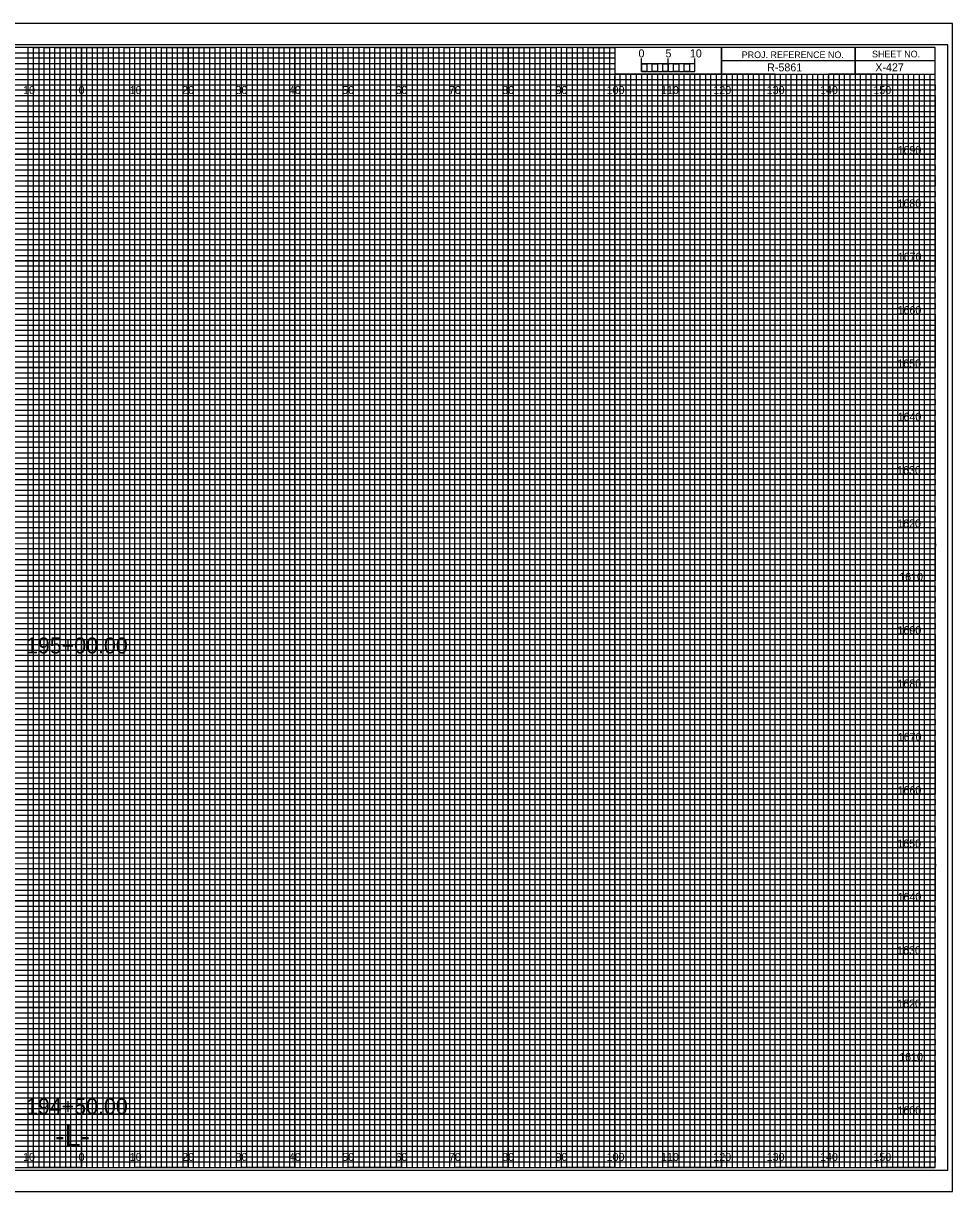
# Model space of a CAD drawing. Extents: x -13 to 323, y -5 to 6154.
# Drawn here: x 149.1 to 323.3, y 5055.5 to 5274.5 of the extents above; entities that cross this region are included whole.
import ezdxf

# ---------------------------------------------------------------- set-up
doc = ezdxf.new("R2010")
doc.units = 0
for name, color, linetype in [('Exist CMT Ground Line', 7, 'Continuous'), ('Prop Horizontal Alignment', 7, 'Continuous'), ('Prop Retaining Wall', 7, 'Continuous'), ('Prop XS Alignment Label', 7, 'Continuous'), ('Prop XS Bar Scale Labels', 7, 'Continuous'), ('Prop XS DDE', 7, 'Continuous'), ('Prop XS DDE Elevations', 7, 'Continuous'), ('Prop XS DDE Slope Text', 7, 'Continuous'), ('Prop XS Earthwork Shape', 7, 'Continuous'), ('Prop XS Elevation Labels', 7, 'Continuous'), ('Prop XS Project Number', 7, 'Continuous'), ('Prop XS Sheet Number', 7, 'Continuous'), ('Prop XS Station Labels', 7, 'Continuous'), ('Raster_Level_0', 7, 'Continuous'), ('Scratch_Level_3', 7, 'Continuous'), ('Sheet Cutting Line CELL', 7, 'Continuous')]:
    doc.layers.add(name, color=color, linetype=linetype)

msp = doc.modelspace()

# ---------------------------------------------------------------- linework, layer by layer
at = {"layer": 'Exist CMT Ground Line'}
for p, q in [((265, 5265.49), (265, 5267.9)), ((265, 5266.9), (265, 5267.9)), ((270, 5265.49), (270, 5267.9)), ((275, 5265.49), (275, 5267.9)), ((275, 5266.9), (275, 5267.9))]:
    msp.add_line(p, q, dxfattribs=at)
for points in [[(275, 5266.9), (265, 5266.9), (265, 5265.49), (275, 5265.49)], [(265, 5266.9), (266, 5266.9), (266, 5265.49), (265, 5265.49)], [(267, 5266.9), (268, 5266.9), (268, 5265.49), (267, 5265.49)], [(269, 5266.9), (270, 5266.9), (270, 5265.49), (269, 5265.49)], [(271, 5266.9), (272, 5266.9), (272, 5265.49), (271, 5265.49)], [(273, 5266.9), (274, 5266.9), (274, 5265.49), (273, 5265.49)]]:
    msp.add_lwpolyline(points, close=True, dxfattribs=at)
at = {"layer": 'Prop Retaining Wall'}
for p, q in [((0, 5269), (260, 5269)), ((260, 5267.98), (0, 5267.98)), ((0, 5267), (260, 5267)), ((260, 5269), (260, 5267.98)), ((260, 5267), (260, 5265.89)), ((260, 5265.89), (0, 5265.89)), ((0, 5264), (320, 5264))]:
    msp.add_line(p, q, dxfattribs=at)
for points in [[(0, 5263), (270, 5263), (320, 5263), (320, 5262), (0, 5262)], [(0, 5261), (320, 5261), (320, 5259), (0, 5259)], [(0, 5258), (320, 5258), (320, 5257), (0, 5256.98)], [(0, 5256), (320, 5256), (320, 5254), (0, 5254)], [(0, 5253), (320, 5253), (320, 5252), (0, 5252)], [(0, 5251), (320, 5251), (320, 5249), (0, 5249)], [(0, 5248), (320, 5248), (320, 5247), (0, 5247)], [(0, 5246), (320, 5246), (320, 5244), (0, 5244)], [(0, 5243), (320, 5243), (320, 5242), (0, 5242)], [(0, 5241), (320, 5241), (320, 5239), (0, 5239)], [(0, 5238), (320, 5238), (320, 5237), (0, 5237)], [(0, 5236), (320, 5236), (320, 5233.95), (320, 5233), (320, 5232), (0, 5232)], [(0, 5234), (320, 5234), (320, 5233), (0, 5233)], [(0, 5231), (320, 5231), (320, 5229), (0, 5229.03)], [(0, 5229.03), (320, 5229), (320, 5228), (0, 5228)], [(0, 5227), (320, 5227), (320, 5226), (0, 5226)], [(0, 5224), (320, 5224), (320, 5223), (0, 5223)], [(0, 5222), (320, 5222), (320, 5221), (0, 5221)], [(-0.07, 5218.89), (320, 5218.89), (320, 5217.88), (-0.07, 5217.88)], [(0, 5217), (320, 5217), (320, 5216), (0, 5216)], [(0, 5214), (320, 5214), (320, 5213), (0, 5213)], [(0, 5212), (320, 5212), (320, 5211), (0, 5211)], [(0, 5209), (320, 5209), (320, 5208), (0, 5208)], [(0, 5207), (320, 5207), (320, 5206), (0, 5206)], [(0, 5204), (320, 5204), (320, 5203), (0, 5203)], [(0, 5202), (320, 5202), (320, 5201), (0, 5201)], [(0, 5199), (320, 5199), (319.99, 5197.98), (0, 5198)], [(0, 5197), (320, 5197), (320, 5196), (0, 5196)], [(0, 5194), (320, 5194), (320, 5193), (0, 5193)], [(0, 5192), (320, 5192), (320, 5191), (0, 5191)], [(0, 5189), (320, 5189), (320, 5188), (0, 5188)], [(0, 5187), (320, 5187), (320, 5186), (0, 5186)], [(0, 5184), (320, 5184), (320, 5183), (0, 5183)], [(0, 5182), (320, 5182), (320, 5181), (0, 5181)], [(0, 5179), (320, 5179), (320, 5178), (0, 5178)], [(0, 5176.99), (320.07, 5176.91), (320, 5176), (0, 5176)], [(0, 5174), (320, 5174), (320, 5173), (0, 5173)], [(0, 5172), (320, 5172), (320, 5171), (0, 5171)], [(0, 5169), (320, 5169), (320, 5168), (0, 5168)], [(0, 5167), (320, 5167), (320, 5166), (0, 5166)], [(0, 5164), (320, 5164), (320, 5163), (0, 5163)], [(0, 5162), (320, 5162), (320, 5161), (0, 5161)], [(0, 5159), (320, 5159), (320, 5158), (0, 5158)], [(0, 5157), (320, 5157), (320, 5156), (0, 5156)], [(0, 5154), (320, 5154), (320, 5153), (0, 5153)], [(0, 5152), (320, 5152), (320, 5151), (0, 5151)], [(0, 5149), (320, 5149), (320, 5148), (0, 5148)], [(0, 5147), (320, 5147), (320, 5146), (0, 5146)], [(0, 5144), (320, 5144), (320, 5143), (0, 5143)], [(0, 5142), (320, 5142), (320, 5141), (0, 5141)], [(0, 5139), (320, 5139), (319.99, 5137.98), (0, 5138)], [(0, 5137), (320, 5137), (320, 5136), (0, 5136)], [(0, 5134), (320, 5134), (320, 5133), (0, 5133)], [(0, 5132), (320, 5132), (320, 5131), (0, 5131)], [(0, 5129), (320, 5129), (320, 5128), (0, 5128)], [(0, 5127), (320, 5127), (320, 5126), (0, 5126)], [(0, 5124), (320, 5124), (320, 5123), (0, 5123)], [(0, 5122), (320, 5122), (320, 5121), (0, 5121)], [(0, 5119), (320, 5119), (320, 5118), (0, 5118)], [(0, 5116.99), (320.07, 5116.91), (320, 5116), (0, 5116)], [(0, 5114), (320, 5114), (320, 5113), (0, 5113)], [(0, 5112), (320, 5112), (320, 5111), (0, 5111)], [(0, 5109), (320, 5109), (320, 5108), (0, 5108)], [(0, 5107), (320, 5107), (320, 5106), (0, 5106)], [(0, 5104), (320, 5104), (320, 5103), (0, 5103)], [(0, 5102), (320, 5102), (320, 5101), (0, 5101)], [(0, 5099), (320, 5099), (320, 5098), (0, 5098)], [(0, 5097), (320, 5097), (320, 5096), (0, 5096)], [(0, 5094), (320, 5094), (320, 5093), (0, 5093)], [(0, 5092), (320, 5092), (320, 5091), (0, 5091)], [(0, 5089), (320, 5089), (320, 5088), (0, 5088)], [(0, 5087), (320, 5087), (320, 5086), (0, 5086)], [(0, 5084), (320, 5084), (320, 5083), (0, 5083)], [(0, 5082), (320, 5082), (320, 5081), (0, 5081)], [(0, 5079), (320, 5079), (320, 5078), (0, 5078)], [(0, 5077), (320, 5077), (320, 5076), (0, 5076)], [(0, 5074), (320, 5074), (320, 5073), (0, 5073)], [(0, 5072), (320, 5072), (320, 5071), (0, 5071)], [(0, 5069), (320, 5069), (320, 5068), (0, 5068)], [(0, 5067), (320, 5067), (320, 5066), (0, 5066)], [(0, 5064), (320, 5064), (320, 5063), (0, 5063)], [(0, 5062), (320, 5062), (320, 5061), (0, 5061)]]:
    msp.add_lwpolyline(points, dxfattribs=at)
at = {"layer": 'Prop XS Alignment Label'}
for p, q in [((305, 5270), (305, 5265)), ((305, 5265), (305, 5270)), ((280, 5267.5), (280, 5265)), ((320, 5267.49), (280, 5267.49)), ((280, 5265), (320, 5265))]:
    msp.add_line(p, q, dxfattribs=at)
for points in [[(320, 5270), (0, 5270), (0, 5060), (320, 5060)], [(280, 5270), (260, 5270), (260, 5265.03), (280, 5265.03)], [(320, 5270), (280, 5270), (280, 5265), (320, 5265)]]:
    msp.add_lwpolyline(points, close=True, dxfattribs=at)
at = {"layer": 'Prop XS DDE'}
msp.add_lwpolyline([(-13.4, 5055.5), (323.3, 5055.5), (323.3, 5274.5), (-13.4, 5274.5)], close=True, dxfattribs=at)
at = {"layer": 'Prop XS DDE Elevations'}
for p, q in [((150, 5060), (150, 5270)), ((160, 5060), (160, 5270)), ((170, 5060), (170, 5270)), ((180, 5060), (180, 5270)), ((190, 5060), (190, 5270)), ((200, 5060), (200, 5270)), ((210, 5060), (210, 5270)), ((220, 5060), (220, 5270)), ((230, 5060), (230, 5270)), ((240, 5060), (240, 5270)), ((250, 5060), (250, 5270)), ((260, 5060), (260, 5264.69)), ((270, 5060), (270, 5264.69)), ((280, 5060), (280, 5264.69)), ((290, 5060), (290, 5264.69)), ((300, 5060), (300, 5264.69)), ((310, 5060), (310, 5264.69)), ((0, 5260), (320, 5260)), ((0, 5250), (320, 5250)), ((0, 5240), (320, 5240)), ((0, 5230), (320, 5230)), ((0, 5220), (320, 5220)), ((0, 5210), (320, 5210)), ((0, 5200), (320, 5200)), ((0, 5190), (320, 5190)), ((0, 5180), (320, 5180)), ((0, 5170), (320, 5170)), ((0, 5160), (320, 5160)), ((0, 5150), (320, 5150)), ((0, 5140), (320, 5140)), ((0, 5130), (320, 5130)), ((0, 5120), (320, 5120)), ((0, 5110), (320, 5110)), ((0, 5100), (320, 5100)), ((0, 5090), (320, 5090)), ((0, 5080), (320, 5080)), ((0, 5070), (320, 5070))]:
    msp.add_line(p, q, dxfattribs=at)
at = {"layer": 'Prop XS DDE Slope Text'}
msp.add_lwpolyline([(-10.8, 5059.5), (322.4, 5059.5), (322.4, 5270.5), (-10.8, 5270.5)], close=True, dxfattribs=at)
at = {"layer": 'Prop XS Earthwork Shape'}
for p, q in [((150, 5270), (140, 5270)), ((150, 5060), (150, 5270)), ((170, 5270), (160, 5270)), ((160, 5270), (160, 5060)), ((170, 5060), (170, 5270)), ((190, 5270), (180, 5270)), ((180, 5270), (180, 5060)), ((190, 5060), (190, 5270)), ((210, 5270), (200, 5270)), ((200, 5270), (200, 5060)), ((210, 5060), (210, 5270)), ((230, 5270), (220, 5270)), ((220, 5270), (220, 5060)), ((230, 5060), (230, 5270)), ((250, 5270), (240, 5270)), ((240, 5270), (240, 5060)), ((250, 5060), (250, 5270)), ((260, 5270), (260, 5060)), ((270, 5060), (270, 5265)), ((290, 5265), (280, 5265)), ((280, 5265), (280, 5060)), ((290, 5060), (290, 5265)), ((310, 5265), (300, 5265)), ((300, 5265), (300, 5060)), ((310, 5060), (310, 5265)), ((160, 5060), (150, 5060)), ((180, 5060), (170, 5060)), ((200, 5060), (190, 5060)), ((220, 5060), (210, 5060)), ((240, 5060), (230, 5060)), ((260, 5060), (250, 5060)), ((280, 5060), (270, 5060)), ((300, 5060), (290, 5060)), ((320, 5060), (310, 5060)), ((320, 5060), (320, 5060))]:
    msp.add_line(p, q, dxfattribs=at)
for points in [[(0, 5260), (320, 5260), (320, 5250), (0, 5250)], [(0, 5240), (320, 5240), (320, 5230), (0, 5230)], [(0, 5220), (320, 5220), (320, 5210), (0, 5210)], [(0, 5200), (320, 5200), (320, 5190), (0, 5190)], [(0, 5180), (320, 5180), (320, 5170), (0, 5170)], [(0, 5160), (320, 5160), (320, 5150), (0, 5150)], [(0, 5140), (320, 5140), (320, 5130), (0, 5130)], [(0, 5120), (320, 5120), (320, 5110), (0, 5110)], [(0, 5100), (320, 5100), (320, 5090), (0, 5090)], [(0, 5080), (320, 5080), (320, 5070), (0, 5070)]]:
    msp.add_lwpolyline(points, dxfattribs=at)
at = {"layer": 'Prop XS Elevation Labels'}
for p, q in [((267, 5265), (266.01, 5265)), ((266.01, 5265), (266.01, 5060)), ((267, 5060), (267, 5265)), ((269, 5265), (268, 5265)), ((268, 5265), (268, 5060)), ((269, 5060), (269, 5265)), ((266.01, 5060), (265, 5060)), ((268, 5060), (267, 5060))]:
    msp.add_line(p, q, dxfattribs=at)
for points in [[(150, 5060), (151, 5060), (151, 5270), (152, 5270), (152, 5060)], [(152, 5060), (153, 5060), (153, 5270), (154, 5270), (154, 5060)], [(155, 5060), (156, 5060), (156, 5270), (157, 5270), (157, 5060)], [(157, 5060), (158, 5060), (158, 5270), (159, 5270), (159, 5060)], [(160, 5060), (161, 5060), (161, 5270), (162, 5270), (162, 5060)], [(162, 5060), (163, 5060), (163, 5270), (164, 5270), (164, 5060)], [(165, 5060), (166, 5060), (166, 5270), (167, 5270), (167, 5060)], [(167, 5060), (168, 5060), (168, 5270), (169, 5270), (169, 5060)], [(170, 5060), (171, 5060), (171, 5270), (172, 5270), (172, 5060)], [(172, 5060), (173, 5060), (173, 5270), (174, 5270), (174, 5060)], [(175, 5060), (176, 5060), (176, 5270), (177, 5270), (177, 5060)], [(177, 5060), (178, 5060), (178, 5270), (179, 5270), (179, 5060)], [(180, 5060), (181, 5060), (181, 5270), (182, 5270), (182, 5060)], [(182, 5060), (183, 5060), (183, 5270), (184, 5270), (184, 5060)], [(185, 5060), (186, 5060), (186, 5270), (187, 5270), (187, 5060)], [(187, 5060), (188, 5060), (188, 5270), (189, 5270), (189, 5060)], [(190, 5060), (191, 5060), (191, 5270), (192, 5270), (192, 5060)], [(192, 5060), (193, 5060), (193, 5270), (194, 5270), (194, 5060)], [(195, 5060), (196, 5060), (196, 5270), (197, 5270), (197, 5060)], [(197, 5060), (198, 5060), (198, 5270), (199, 5270), (199, 5060)], [(200, 5060), (201, 5060), (201, 5270), (202, 5270), (202, 5060)], [(202, 5060), (203, 5060), (203, 5270), (204, 5270), (204, 5060)], [(205, 5060), (206, 5060), (206, 5270), (207, 5270), (207, 5060)], [(207, 5060), (208, 5060), (208, 5270), (209, 5270), (209, 5060)], [(210, 5060), (211, 5060), (211, 5270), (212, 5270), (212, 5060)], [(212, 5060), (213, 5060), (213, 5270), (214, 5270), (214, 5060)], [(215, 5060), (216, 5060), (216, 5270), (217, 5270), (217, 5060)], [(217, 5060), (218, 5060), (218, 5270), (219, 5270), (219, 5060)], [(220, 5060), (221, 5060), (221, 5270), (222, 5270), (222, 5060)], [(222, 5060), (223, 5060), (223, 5270), (224, 5270), (224, 5060)], [(225, 5060), (226, 5060), (226, 5270), (227, 5270), (227, 5060)], [(227, 5060), (228, 5060), (228, 5270), (229, 5270), (229, 5060)], [(230, 5060), (231, 5060), (231, 5270), (232, 5270), (232, 5060)], [(232, 5060), (233, 5060), (233, 5270), (234, 5270), (234, 5060)], [(235, 5060), (236, 5060), (236, 5270), (237, 5270), (237, 5060)], [(237, 5060), (238, 5060), (238, 5270), (239, 5270), (239, 5060)], [(240, 5060), (241, 5060), (241, 5270), (242, 5270), (242, 5060)], [(242, 5060), (243, 5060), (243, 5270), (244, 5270), (244, 5060)], [(245, 5060), (246, 5060), (246, 5270), (247, 5270), (247, 5060)], [(247, 5060), (248, 5060), (248, 5270), (249, 5270), (249, 5060)], [(250, 5060), (251, 5060), (251, 5270), (252, 5270), (252, 5060)], [(252, 5060), (253, 5060), (253, 5270), (254, 5270), (254, 5060)], [(255, 5060), (256, 5060), (256, 5270), (257, 5270), (257, 5060)], [(257, 5060), (258, 5060), (258, 5270), (259, 5270), (259, 5060)], [(260, 5060), (261, 5060), (261, 5265), (262.02, 5265), (262.02, 5060)], [(262, 5060), (263, 5060), (263, 5265), (263.99, 5265), (263.99, 5060)], [(270, 5060), (270.98, 5060), (270.98, 5265), (272, 5265), (272, 5060)], [(272, 5060), (273, 5060), (273, 5265), (274.05, 5265), (274.05, 5060)], [(275, 5060), (276, 5060), (276, 5265), (277, 5265), (277, 5060)], [(277, 5060), (278, 5060), (278, 5265), (279, 5265), (279, 5060)], [(280, 5060), (281, 5060), (281, 5265), (282, 5265), (282, 5060)], [(282, 5060), (283, 5060), (283, 5265), (284, 5265), (284, 5060)], [(285, 5060), (286, 5060), (286, 5265), (287, 5265), (287, 5060)], [(287, 5060), (288, 5060), (288, 5265), (289, 5265), (289, 5060)], [(290, 5060), (291, 5060), (291, 5265), (292, 5265), (292, 5060)], [(292, 5060), (293, 5060), (293, 5265), (294, 5265), (294, 5060)], [(295, 5060), (296, 5060), (296, 5265), (297, 5265), (297, 5060)], [(297, 5060), (298, 5060), (298, 5265), (299, 5265), (299, 5060)], [(300, 5060), (301, 5060), (301, 5265), (302, 5265), (302, 5060)], [(302, 5060), (303, 5060), (303, 5265), (304, 5265), (304, 5060)], [(305, 5060), (306, 5060), (306, 5265), (307, 5265), (307, 5060)], [(307, 5060), (308, 5060), (308, 5265), (309, 5265), (309, 5060)], [(310, 5060), (311, 5060), (311, 5265), (312, 5265), (312, 5060)], [(312, 5060), (313, 5060), (313, 5265), (314, 5265), (314, 5060)], [(315, 5060), (316, 5060), (316, 5265), (317, 5265), (317, 5060)], [(317, 5060), (318, 5060), (318, 5265), (319, 5265), (319, 5060)]]:
    msp.add_lwpolyline(points, dxfattribs=at)
at = {"layer": 'Prop XS Station Labels'}
for points in [[(145, 5060), (155, 5060), (155, 5270), (165, 5270), (165, 5060), (175, 5060), (175, 5270), (185, 5270), (185, 5060), (195, 5060), (195, 5270), (205, 5270), (205, 5060), (215, 5060), (215, 5270), (225, 5270), (225, 5060), (235, 5060), (235, 5270), (245, 5270), (245, 5060), (255, 5060), (255, 5270), (259.93, 5270), (260, 5270), (260, 5265), (264.99, 5265), (264.99, 5060), (275, 5060), (275, 5265), (285, 5265), (285, 5060), (295, 5060), (295, 5265), (305, 5265), (305, 5060), (315, 5060), (315, 5265)], [(0, 5265), (275, 5265)], [(0, 5245), (320, 5245), (320, 5255), (0, 5255)], [(0, 5225), (320, 5225), (320, 5235), (0, 5235)], [(0, 5205), (320, 5205), (320, 5215), (0, 5215)], [(0, 5185), (320, 5185), (320, 5195), (0, 5195)], [(0, 5165), (320, 5165), (320, 5175), (0, 5175)], [(0, 5145), (320, 5145), (320, 5155), (0, 5155)], [(0, 5125), (320, 5125), (320, 5135), (0, 5135)], [(0, 5105), (320, 5105), (320, 5115), (0, 5115)], [(0, 5085), (320, 5085), (320, 5095), (0, 5095)], [(0, 5065), (320, 5065), (320, 5075), (0, 5075)]]:
    msp.add_lwpolyline(points, dxfattribs=at)
at = {"layer": 'Sheet Cutting Line CELL'}
for p, q in [((323.3, 5274.5), (-13.4, 5274.5)), ((-13.4, 5055.5), (323.3, 5055.5))]:
    msp.add_line(p, q, dxfattribs=at)

# ---------------------------------------------------------------- texts
at = {"layer": 'Exist CMT Ground Line'}
msp.add_text('0', height=1.5, dxfattribs=at).set_placement((264.41, 5268.12))
at = {"layer": 'Prop Horizontal Alignment'}
for s, p in [('195+00.00', (149.59, 5156.38)), ('194+50.00', (149.59, 5070))]:
    msp.add_text(s, height=3, dxfattribs=at).set_placement(p)
at = {"layer": 'Prop XS Alignment Label'}
for s, height, p in [('PROJ. REFERENCE NO.', 1.25, (283.77, 5267.99)), ('SHEET NO.', 1.25, (308.19, 5268.12)), ('-L-', 4, (155.06, 5064))]:
    msp.add_text(s, height=height, dxfattribs=at).set_placement(p)
at = {"layer": 'Prop XS Bar Scale Labels'}
for s, p in [('5', (269.47, 5268.12)), ('10', (274.04, 5268.12))]:
    msp.add_text(s, height=1.5, dxfattribs=at).set_placement(p)
at = {"layer": 'Prop XS Project Number'}
msp.add_text('R-5861', height=1.5, dxfattribs=at).set_placement((288.53, 5265.5))
at = {"layer": 'Prop XS Sheet Number'}
msp.add_text('X-427', height=1.5, dxfattribs=at).set_placement((308.8, 5265.51))
at = {"layer": 'Raster_Level_0'}
for s, p in [('10', (149.04, 5261.25)), ('0', (159.45, 5261.25)), ('0', (159.45, 5261.25)), ('10', (169.04, 5261.25)), ('20', (178.86, 5261.25)), ('30', (188.86, 5261.25)), ('40', (198.86, 5261.25)), ('50', (208.86, 5261.25)), ('60', (218.86, 5261.25)), ('70', (228.86, 5261.25)), ('80', (238.86, 5261.25)), ('90', (248.86, 5261.25)), ('100', (258.44, 5261.25)), ('110', (268.62, 5261.25)), ('120', (278.44, 5261.25)), ('130', (288.44, 5261.25)), ('140', (298.44, 5261.25)), ('150', (308.44, 5261.25)), ('10', (149.04, 5061.25)), ('0', (159.45, 5061.25)), ('0', (159.45, 5061.25)), ('10', (169.04, 5061.25)), ('20', (178.86, 5061.25)), ('30', (188.86, 5061.25)), ('40', (198.86, 5061.25)), ('50', (208.86, 5061.25)), ('60', (218.86, 5061.25)), ('70', (228.86, 5061.25)), ('80', (238.86, 5061.25)), ('90', (248.86, 5061.25)), ('100', (258.44, 5061.25)), ('110', (268.62, 5061.25)), ('120', (278.44, 5061.25)), ('130', (288.44, 5061.25)), ('140', (298.44, 5061.25)), ('150', (308.44, 5061.25))]:
    msp.add_text(s, height=1.5, dxfattribs=at).set_placement(p)
at = {"layer": 'Scratch_Level_3'}
for s, p in [('1690', (312.97, 5250)), ('1680', (312.95, 5240)), ('1670', (313, 5230)), ('1660', (312.97, 5220)), ('1650', (312.92, 5210)), ('1640', (312.97, 5200)), ('1630', (312.89, 5190)), ('1620', (312.9, 5180)), ('1610', (313.28, 5170)), ('1600', (312.95, 5160)), ('1690', (312.97, 5160)), ('1680', (312.95, 5150)), ('1670', (313, 5140)), ('1660', (312.97, 5130)), ('1650', (312.92, 5120)), ('1640', (312.97, 5110)), ('1630', (312.89, 5100)), ('1620', (312.9, 5090)), ('1610', (313.28, 5080)), ('1600', (312.95, 5070))]:
    msp.add_text(s, height=1.5, dxfattribs=at).set_placement(p)

doc.saveas('drawing.dxf')
